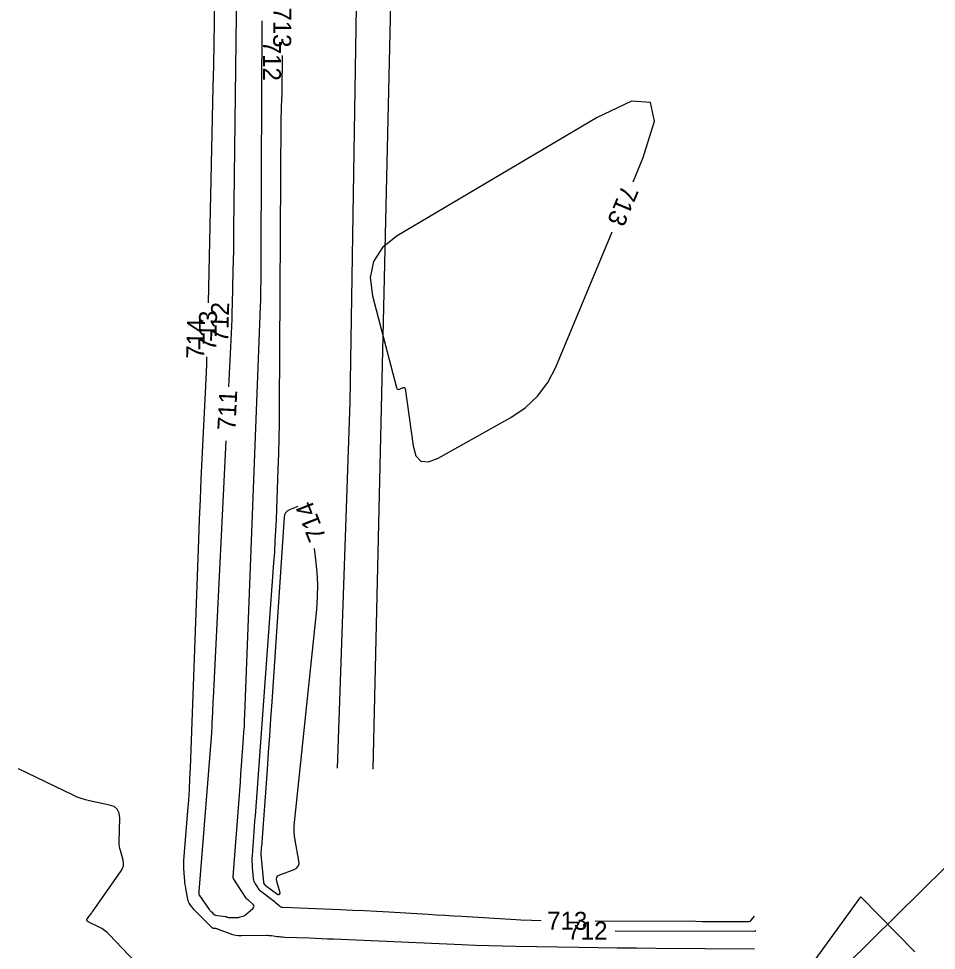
# Model space of a CAD drawing. Extents: x -468548933 to 3387700, y -306089263 to 1207014.
# Drawn here: x 1835186 to 1835389.9, y 536291.2 to 536498.1 of the extents above; entities that cross this region are included whole.
import ezdxf

# ---------------------------------------------------------------- set-up
doc = ezdxf.new("R2010")
doc.units = 0
for name, color, linetype in [('DT_X_Contour_Minor', 7, 'Continuous'), ('Level 19', 7, 'Continuous'), ('Level 40', 7, 'Continuous'), ('Level 56', 7, 'Continuous')]:
    doc.layers.add(name, color=color, linetype=linetype)

msp = doc.modelspace()

# ---------------------------------------------------------------- linework, layer by layer
at = {"layer": 'DT_X_Contour_Minor'}
for points in [[(1835228.14, 536435.01), (1835229.23, 536482.95), (1835229.33, 536487.76), (1835229.42, 536492.57), (1835229.5, 536497.39), (1835229.56, 536502.2), (1835229.74, 536517.93), (1835229.78, 536521.3), (1835229.82, 536524.67), (1835229.86, 536528.04), (1835229.89, 536531.42), (1835230.34, 536574.57), (1835230.4, 536580.55), (1835230.43, 536586.52), (1835230.44, 536592.5), (1835230.43, 536598.47), (1835230.36, 536617.99), (1835230.36, 536622.17), (1835230.37, 536626.35), (1835230.4, 536630.53), (1835230.44, 536634.72), (1835231.06, 536683.36), (1835231.08, 536684.99)], [(1835234.67, 536528.87), (1835233.76, 536451.31), (1835233.73, 536449.02), (1835233.7, 536446.73), (1835233.66, 536444.43), (1835233.61, 536442.14), (1835233.44, 536434.65), (1835233.39, 536433.05), (1835233.34, 536431.44), (1835233.28, 536429.84), (1835233.2, 536428.23), (1835232.61, 536416.35)], [(1835228.83, 536339.42), (1835225.99, 536304.27), (1835225.99, 536304.21), (1835225.99, 536304.16), (1835225.99, 536304.1), (1835225.99, 536304.05), (1835226, 536303.87), (1835226.01, 536303.83), (1835226.01, 536303.79), (1835226.02, 536303.75), (1835226.02, 536303.72), (1835226.06, 536303.5), (1835226.07, 536303.46), (1835226.09, 536303.41), (1835226.11, 536303.37), (1835226.14, 536303.33), (1835228.34, 536300.27), (1835228.46, 536300.11), (1835228.58, 536299.96), (1835228.71, 536299.82), (1835228.84, 536299.68), (1835229.29, 536299.23), (1835229.39, 536299.14), (1835229.5, 536299.07), (1835229.62, 536299.03), (1835229.75, 536299), (1835231.86, 536298.69), (1835231.95, 536298.67), (1835232.04, 536298.65), (1835232.13, 536298.63), (1835232.22, 536298.59), (1835232.51, 536298.48), (1835232.57, 536298.46), (1835232.64, 536298.45), (1835232.7, 536298.44), (1835232.77, 536298.44), (1835234.41, 536298.46), (1835234.61, 536298.47), (1835234.82, 536298.49), (1835235.02, 536298.52), (1835235.22, 536298.57), (1835235.87, 536298.75), (1835236, 536298.8), (1835236.13, 536298.86), (1835236.25, 536298.93), (1835236.36, 536299.02), (1835238.11, 536300.55), (1835238.28, 536300.75), (1835238.34, 536300.95), (1835238.28, 536301.16), (1835238.11, 536301.36), (1835237.16, 536302.2), (1835237.1, 536302.25), (1835237.03, 536302.3), (1835236.97, 536302.35), (1835236.9, 536302.4), (1835236.69, 536302.56), (1835236.65, 536302.6), (1835236.61, 536302.64), (1835236.57, 536302.68), (1835236.54, 536302.73), (1835233.77, 536306.95), (1835233.74, 536306.99), (1835233.72, 536307.04), (1835233.71, 536307.09), (1835233.7, 536307.14), (1835233.68, 536307.32), (1835233.68, 536307.36), (1835233.68, 536307.39), (1835233.68, 536307.43), (1835233.68, 536307.47), (1835234.97, 536324.77), (1835235.11, 536326.64), (1835235.25, 536328.5), (1835235.39, 536330.37), (1835235.53, 536332.24), (1835235.97, 536338.33), (1835236.06, 536339.64), (1835236.14, 536340.95), (1835236.21, 536342.26), (1835236.27, 536343.56), (1835239.72, 536434.2), (1835239.77, 536435.56), (1835239.8, 536436.93), (1835239.83, 536438.3), (1835239.84, 536439.67), (1835239.88, 536445.84), (1835239.88, 536445.95), (1835239.88, 536446.06), (1835239.88, 536446.17), (1835239.89, 536446.28), (1835239.9, 536446.63), (1835239.9, 536446.71), (1835239.9, 536446.79), (1835239.91, 536446.86), (1835239.91, 536446.94), (1835240.11, 536497.65)], [(1835244.52, 536489.97), (1835244.52, 536489.68), (1835244.52, 536488.68), (1835244.51, 536487.68), (1835244.5, 536484.4), (1835244.49, 536483.7), (1835244.48, 536483), (1835244.46, 536482.3), (1835244.44, 536481.6), (1835244.33, 536478.54), (1835244.31, 536477.89), (1835244.29, 536477.23), (1835244.28, 536476.58), (1835244.27, 536475.92), (1835243.91, 536411.73), (1835243.87, 536408.31), (1835243.81, 536404.88), (1835243.72, 536401.45), (1835243.61, 536398.03), (1835243.18, 536386.84), (1835243.08, 536384.44), (1835242.95, 536382.05), (1835242.81, 536379.65), (1835242.64, 536377.26), (1835238.52, 536321.06), (1835238.43, 536319.89), (1835238.35, 536318.72), (1835238.26, 536317.55), (1835238.17, 536316.38), (1835237.87, 536312.26), (1835237.83, 536311.59), (1835237.82, 536310.92), (1835237.84, 536310.25), (1835237.89, 536309.58), (1835238.12, 536307.09), (1835238.17, 536306.78), (1835238.25, 536306.48), (1835238.37, 536306.2), (1835238.53, 536305.92), (1835239.1, 536305.05), (1835239.23, 536304.87), (1835239.37, 536304.71), (1835239.53, 536304.55), (1835239.7, 536304.41), (1835241.9, 536302.76), (1835242.18, 536302.54), (1835242.45, 536302.32), (1835242.73, 536302.1), (1835242.99, 536301.86), (1835243.86, 536301.1), (1835244.05, 536300.96), (1835244.26, 536300.85), (1835244.49, 536300.78), (1835244.73, 536300.75), (1835257.52, 536300.23), (1835260.2, 536300.12), (1835262.87, 536299.99), (1835265.55, 536299.85), (1835268.22, 536299.69), (1835276.96, 536299.17), (1835278.83, 536299.06), (1835280.71, 536298.95), (1835282.58, 536298.83), (1835284.45, 536298.72), (1835295.27, 536298.06), (1835297.59, 536297.94), (1835299.91, 536297.85), (1835302.1, 536297.79)], [(1835322.5, 536461.86), (1835324.78, 536467.31), (1835327.27, 536475.35), (1835326.39, 536479.52), (1835322.14, 536479.81), (1835314.53, 536476.22), (1835270.12, 536449.86), (1835266.87, 536447.3), (1835264.87, 536444.22), (1835264.13, 536440.63), (1835264.64, 536436.53)], [(1835264.64, 536436.53), (1835269.92, 536416.17), (1835270.02, 536415.94), (1835270.16, 536415.81), (1835270.35, 536415.78), (1835270.59, 536415.84), (1835271.45, 536416.19), (1835271.62, 536416.23), (1835271.74, 536416.21), (1835271.83, 536416.11), (1835271.87, 536415.95), (1835273.63, 536403.26), (1835274.26, 536401.05), (1835275.39, 536399.85), (1835277.03, 536399.67), (1835279.17, 536400.5), (1835295.34, 536409.55), (1835298.56, 536411.71), (1835301.3, 536414.29), (1835303.55, 536417.31), (1835305.33, 536420.75), (1835317.88, 536450.79)], [(1835349.5, 536291.45), (1835327.57, 536291.58), (1835323.28, 536291.61), (1835319, 536291.65), (1835314.72, 536291.7), (1835310.45, 536291.77), (1835296.46, 536292.01), (1835293.47, 536292.07), (1835290.47, 536292.15), (1835287.48, 536292.25), (1835284.49, 536292.38), (1835255.97, 536293.62), (1835254.62, 536293.68), (1835253.27, 536293.74), (1835251.92, 536293.79), (1835250.56, 536293.84), (1835245.05, 536294.04), (1835244.65, 536294.06), (1835244.25, 536294.09), (1835243.85, 536294.13), (1835243.45, 536294.18), (1835242.15, 536294.37), (1835241.87, 536294.4), (1835241.59, 536294.42), (1835241.31, 536294.44), (1835241.03, 536294.44), (1835235.51, 536294.37), (1835234.86, 536294.4), (1835234.22, 536294.48), (1835233.59, 536294.63), (1835232.97, 536294.83), (1835230.41, 536295.82), (1835230.26, 536295.87), (1835230.11, 536295.92), (1835229.95, 536295.95), (1835229.8, 536295.98), (1835229.28, 536296.05), (1835229.18, 536296.08), (1835229.08, 536296.12), (1835228.99, 536296.17), (1835228.91, 536296.24), (1835224.99, 536300.19), (1835224.82, 536300.36), (1835224.67, 536300.54), (1835224.52, 536300.73), (1835224.37, 536300.92), (1835223.92, 536301.55), (1835223.83, 536301.69), (1835223.76, 536301.83), (1835223.7, 536301.99), (1835223.66, 536302.15), (1835223.14, 536304.92), (1835223.04, 536305.51), (1835222.95, 536306.11), (1835222.89, 536306.7), (1835222.84, 536307.31), (1835222.7, 536309.34), (1835222.68, 536309.78), (1835222.67, 536310.21), (1835222.68, 536310.65), (1835222.71, 536311.09), (1835223.6, 536322.16), (1835223.78, 536324.54), (1835223.93, 536326.91), (1835224.06, 536329.29), (1835224.16, 536331.67), (1835226.01, 536382.39), (1835226.18, 536386.88), (1835226.37, 536391.36), (1835226.57, 536395.85), (1835226.78, 536400.34), (1835227.51, 536414.99), (1835227.66, 536418.13), (1835227.78, 536421.27), (1835227.84, 536423.02)], [(1835232.02, 536404.37), (1835229.18, 536347.21), (1835229.14, 536346.44), (1835229.11, 536345.66), (1835229.08, 536344.89), (1835229.05, 536344.11), (1835228.95, 536341.59), (1835228.93, 536341.04), (1835228.9, 536340.5), (1835228.87, 536339.96), (1835228.83, 536339.42)], [(1835248, 536389.78), (1835246.15, 536389.01), (1835245.67, 536388.74), (1835245.31, 536388.38), (1835245.08, 536387.93), (1835244.98, 536387.38), (1835242.24, 536346.36), (1835241.98, 536342.61), (1835241.72, 536338.85), (1835241.45, 536335.1), (1835241.18, 536331.35), (1835239.92, 536314.18), (1835239.91, 536314.01), (1835239.9, 536313.83), (1835239.88, 536313.66), (1835239.87, 536313.49), (1835239.83, 536312.92), (1835239.82, 536312.8), (1835239.82, 536312.68), (1835239.82, 536312.56), (1835239.83, 536312.44)], [(1835239.83, 536312.44), (1835240.39, 536306.33), (1835240.41, 536306.25), (1835240.43, 536306.17), (1835240.46, 536306.1), (1835240.5, 536306.03), (1835240.65, 536305.8), (1835240.68, 536305.76), (1835240.72, 536305.71), (1835240.76, 536305.67), (1835240.8, 536305.64), (1835243.55, 536303.57), (1835243.62, 536303.53), (1835243.7, 536303.52), (1835243.77, 536303.53), (1835243.84, 536303.58), (1835244.06, 536303.77), (1835244.1, 536303.81), (1835244.13, 536303.86), (1835244.13, 536303.91), (1835244.12, 536303.97), (1835243.33, 536306.49), (1835243.25, 536306.98), (1835243.34, 536307.39), (1835243.61, 536307.72), (1835244.05, 536307.96), (1835247.18, 536309.12), (1835247.75, 536309.43), (1835248.12, 536309.85), (1835248.29, 536310.38), (1835248.26, 536311.03), (1835247.44, 536315.61), (1835247.29, 536316.6), (1835247.22, 536317.59), (1835247.22, 536318.57), (1835247.29, 536319.57), (1835252.23, 536366.91), (1835252.43, 536369.66), (1835252.47, 536372.41), (1835252.34, 536375.16), (1835252.04, 536377.91), (1835251.7, 536380.42)], [(1835209.18, 536311.2), (1835208.59, 536313.31), (1835208.48, 536313.77), (1835208.4, 536314.23), (1835208.36, 536314.69), (1835208.35, 536315.16), (1835208.44, 536320.62), (1835208.31, 536321.67), (1835207.89, 536322.49), (1835207.19, 536323.08), (1835206.19, 536323.44), (1835201.76, 536324.36), (1835200.82, 536324.59), (1835199.91, 536324.87), (1835199.01, 536325.21), (1835198.12, 536325.6), (1835185.99, 536331.46)], [(1835217.63, 536282.56), (1835206.14, 536294.66), (1835205.63, 536295.15), (1835205.08, 536295.59), (1835204.5, 536295.99), (1835203.87, 536296.33), (1835201.43, 536297.53), (1835201.22, 536297.67), (1835201.12, 536297.85), (1835201.14, 536298.05), (1835201.27, 536298.27), (1835201.89, 536299.05), (1835202.03, 536299.22), (1835202.16, 536299.39), (1835202.28, 536299.56), (1835202.41, 536299.73), (1835208.77, 536308.8), (1835209.09, 536309.36), (1835209.26, 536309.95), (1835209.29, 536310.56), (1835209.18, 536311.2)], [(1835314.1, 536297.71), (1835336.46, 536297.61), (1835337.86, 536297.6), (1835339.25, 536297.59), (1835340.65, 536297.59), (1835342.04, 536297.58), (1835348.11, 536297.56), (1835348.32, 536297.58), (1835348.51, 536297.64), (1835348.68, 536297.75), (1835348.83, 536297.91), (1835349.46, 536298.73)], [(1835318.55, 536295.52), (1835349.56, 536295.39), (1835349.6, 536295.4), (1835349.63, 536295.41), (1835349.67, 536295.43), (1835349.69, 536295.46), (1835349.81, 536295.61)]]:
    msp.add_lwpolyline(points, dxfattribs=at)
at = {"layer": 'Level 40'}
for p, q in [((1835342.42, 536260.75), (1835373.1, 536303.07)), ((1835373.1, 536303.07), (1835385.15, 536290.86))]:
    msp.add_line(p, q, dxfattribs=at)
msp.add_lwpolyline([(1835342.41, 536260.74), (1835447.26, 536364.23), (1835491.9, 536378.72)], dxfattribs=at)
at = {"layer": 'Level 56'}
for points in [[(1835262.92, 536746.95), (1835262.45, 536659.53), (1835261.24, 536514.73), (1835259.56, 536412.94), (1835256.79, 536331.65)], [(1835264.78, 536331.38), (1835269.59, 536539.91), (1835270.92, 536746.94)]]:
    msp.add_lwpolyline(points, dxfattribs=at)

# ---------------------------------------------------------------- texts
at = {"layer": 'Level 19'}
for s, rotation, p in [('713', 269.5339, (1835242.61, 536500.67)), ('712', 269.7734, (1835240.31, 536493.26)), ('713', 247.3195, (1835320.15, 536461.41)), ('712', 88.1998, (1835232.51, 536426.18)), ('713', 88.5767, (1835229.88, 536424.29)), ('714', 88.6942, (1835227.2, 536422.52)), ('711', 87.1563, (1835234.13, 536406.61)), ('714', 111.5519, (1835254.38, 536382.93)), ('713', 359.6331, (1835303.41, 536295.77)), ('712', 359.7594, (1835307.89, 536293.57))]:
    msp.add_text(s, height=4, rotation=rotation, dxfattribs=at).set_placement(p)

doc.saveas('drawing.dxf')
